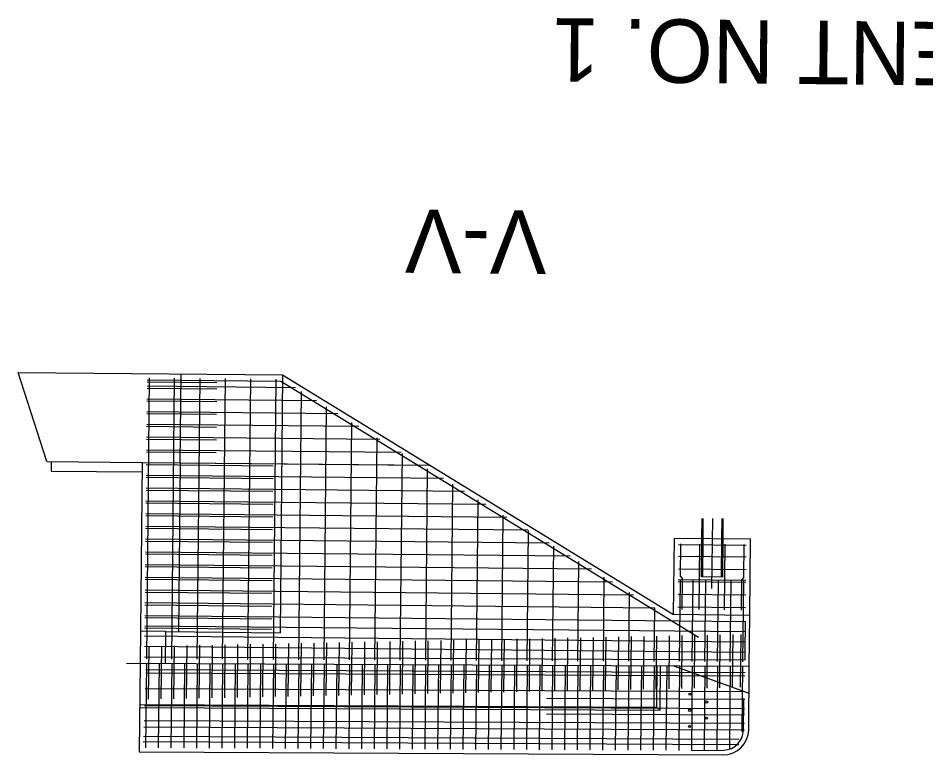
# Model space of a CAD drawing. Extents: x 631918 to 632319, y 373181 to 373282.
# Drawn here: x 632132.56 to 632168.31, y 373221.98 to 373251.01 of the extents above; entities that cross this region are included whole.
import ezdxf

# ---------------------------------------------------------------- set-up
doc = ezdxf.new("R2010")
doc.units = 0
for name, color, linetype in [('B_Boring', 7, 'Continuous'), ('BD-PROP-COSS', 7, 'Continuous'), ('BD-REMOVE', 7, 'Continuous'), ('R_Border_Scale', 7, 'Continuous'), ('R_Road Edge of Travel', 7, 'Continuous'), ('R_Shade Removal', 7, 'Continuous'), ('R_Wall', 7, 'Continuous')]:
    doc.layers.add(name, color=color, linetype=linetype)

msp = doc.modelspace()

# ---------------------------------------------------------------- linework, layer by layer
at = {"layer": 'B_Boring'}
for p, q in [((632157.719, 373223.868), (632157.735, 373225.496)), ((632157.842, 373223.745), (632157.86, 373225.495)), ((632137.342, 373223.846), (632157.842, 373223.745)), ((632137.344, 373223.969), (632157.719, 373223.868)), ((632157.719, 373223.868), (632157.842, 373223.745))]:
    msp.add_line(p, q, dxfattribs=at)
at = {"layer": 'BD-PROP-COSS'}
for p, q in [((632137.721, 373236.838), (632137.611, 373225.763)), ((632140.386, 373236.645), (632137.636, 373236.673)), ((632137.637, 373236.756), (632142.901, 373236.704)), ((632138.611, 373225.758), (632138.721, 373236.828)), ((632139.611, 373225.753), (632139.721, 373236.818)), ((632140.611, 373225.748), (632140.721, 373236.809)), ((632141.611, 373225.743), (632141.721, 373236.799)), ((632142.611, 373225.738), (632142.721, 373236.789)), ((632142.901, 373236.704), (632159.355, 373226.616)), ((632140.384, 373236.395), (632137.634, 373236.423)), ((632143.478, 373236.448), (632137.635, 373236.506)), ((632143.611, 373225.733), (632143.716, 373236.301)), ((632140.379, 373235.893), (632137.629, 373235.92)), ((632144.311, 373235.937), (632137.63, 373236.004)), ((632145.144, 373235.427), (632137.625, 373235.501)), ((632144.611, 373225.728), (632144.71, 373235.692)), ((632140.374, 373235.391), (632137.624, 373235.418)), ((632140.369, 373234.888), (632137.619, 373234.916)), ((632145.977, 373234.916), (632137.62, 373234.999)), ((632145.611, 373225.724), (632145.704, 373235.083)), ((632140.364, 373234.386), (632137.614, 373234.413)), ((632146.809, 373234.405), (632137.615, 373234.497)), ((632146.611, 373225.719), (632146.698, 373234.473)), ((632140.359, 373233.884), (632137.609, 373233.911)), ((632147.642, 373233.895), (632137.61, 373233.994)), ((632147.611, 373225.714), (632147.692, 373233.864)), ((632142.604, 373233.359), (632137.604, 373233.409)), ((632148.475, 373233.384), (632137.605, 373233.492)), ((632149.308, 373232.873), (632137.6, 373232.99)), ((632148.611, 373225.709), (632148.686, 373233.255)), ((632142.599, 373232.857), (632137.599, 373232.906)), ((632149.611, 373225.704), (632149.68, 373232.645)), ((632142.594, 373232.354), (632137.594, 373232.404)), ((632150.141, 373232.363), (632137.595, 373232.488)), ((632142.589, 373231.852), (632137.589, 373231.902)), ((632150.974, 373231.852), (632137.59, 373231.985)), ((632150.611, 373225.699), (632150.674, 373232.036)), ((632142.584, 373231.35), (632137.584, 373231.4)), ((632151.807, 373231.342), (632137.585, 373231.483)), ((632151.611, 373225.694), (632151.668, 373231.426)), ((632142.579, 373230.848), (632137.579, 373230.897)), ((632152.64, 373230.831), (632137.58, 373230.981)), ((632152.611, 373225.689), (632152.662, 373230.817)), ((632153.473, 373230.32), (632137.575, 373230.478)), ((632142.574, 373230.345), (632137.574, 373230.395)), ((632153.611, 373225.684), (632153.656, 373230.208)), ((632161.24, 373230.229), (632158.574, 373230.256)), ((632158.645, 373229.005), (632158.657, 373230.297)), ((632159.382, 373227.706), (632159.407, 373230.289)), ((632160.382, 373227.696), (632160.407, 373230.279)), ((632161.145, 373228.98), (632161.157, 373230.272)), ((632142.569, 373229.843), (632137.569, 373229.893)), ((632154.306, 373229.81), (632137.57, 373229.976)), ((632161.236, 373229.771), (632158.569, 373229.797)), ((632142.564, 373229.341), (632137.564, 373229.39)), ((632155.139, 373229.299), (632137.565, 373229.474)), ((632154.611, 373225.679), (632154.65, 373229.598)), ((632161.231, 373229.271), (632158.564, 373229.297)), ((632142.559, 373228.838), (632137.559, 373228.888)), ((632155.971, 373228.788), (632137.56, 373228.972)), ((632155.611, 373225.674), (632155.644, 373228.989)), ((632161.226, 373228.771), (632158.559, 373228.797)), ((632161.227, 373228.854), (632158.56, 373228.881)), ((632158.611, 373225.672), (632158.643, 373228.88)), ((632158.645, 373229.005), (632158.727, 373228.921)), ((632158.715, 373227.713), (632158.727, 373228.921)), ((632159.111, 373225.667), (632159.143, 373228.875)), ((632159.611, 373225.662), (632159.643, 373228.87)), ((632160.111, 373225.657), (632160.143, 373228.865)), ((632160.611, 373225.652), (632160.643, 373228.86)), ((632161.048, 373227.689), (632161.06, 373228.898)), ((632161.145, 373228.98), (632161.06, 373228.898)), ((632161.111, 373225.647), (632161.143, 373228.855)), ((632142.554, 373228.336), (632137.554, 373228.386)), ((632156.804, 373228.278), (632137.555, 373228.469)), ((632156.611, 373225.669), (632156.638, 373228.38)), ((632157.637, 373227.767), (632137.55, 373227.967)), ((632161.221, 373228.271), (632158.554, 373228.297)), ((632142.549, 373227.834), (632137.549, 373227.884)), ((632157.611, 373225.664), (632157.632, 373227.77)), ((632161.216, 373227.771), (632158.549, 373227.797)), ((632142.544, 373227.332), (632137.544, 373227.381)), ((632161.21, 373227.229), (632137.545, 373227.465)), ((632142.54, 373226.927), (632137.54, 373226.977)), ((632161.206, 373226.825), (632137.541, 373227.06)), ((632161.202, 373226.42), (632137.537, 373226.655)), ((632151.203, 373226.53), (632151.182, 373224.447)), ((632151.703, 373226.54), (632151.682, 373224.457)), ((632152.203, 373226.55), (632152.183, 373224.467)), ((632152.703, 373226.56), (632152.683, 373224.477)), ((632153.203, 373226.57), (632153.183, 373224.487)), ((632153.704, 373226.58), (632153.683, 373224.497)), ((632154.204, 373226.59), (632154.183, 373224.507)), ((632154.704, 373226.6), (632154.683, 373224.517)), ((632155.204, 373226.61), (632155.183, 373224.527)), ((632155.704, 373226.62), (632155.683, 373224.537)), ((632156.204, 373226.63), (632156.184, 373224.547)), ((632156.704, 373226.64), (632156.684, 373224.557)), ((632157.204, 373226.65), (632157.184, 373224.567)), ((632157.705, 373226.66), (632157.684, 373224.577)), ((632158.205, 373226.67), (632158.184, 373224.587)), ((632158.705, 373226.68), (632158.684, 373224.597)), ((632159.205, 373226.691), (632159.184, 373224.607)), ((632159.705, 373226.701), (632159.684, 373224.617)), ((632160.205, 373226.711), (632160.185, 373224.627)), ((632160.705, 373226.721), (632160.685, 373224.637)), ((632161.018, 373224.644), (632161.039, 373226.727)), ((632161.198, 373226.015), (632137.533, 373226.251)), ((632137.7, 373226.259), (632137.679, 373224.176)), ((632138.2, 373226.269), (632138.179, 373224.186)), ((632138.7, 373226.279), (632138.679, 373224.196)), ((632139.2, 373226.289), (632139.179, 373224.206)), ((632139.7, 373226.299), (632139.679, 373224.216)), ((632140.2, 373226.309), (632140.18, 373224.226)), ((632140.7, 373226.319), (632140.68, 373224.236)), ((632141.201, 373226.329), (632141.18, 373224.246)), ((632141.701, 373226.34), (632141.68, 373224.256)), ((632142.201, 373226.35), (632142.18, 373224.266)), ((632142.701, 373226.36), (632142.68, 373224.276)), ((632143.201, 373226.37), (632143.18, 373224.286)), ((632143.701, 373226.38), (632143.68, 373224.296)), ((632144.201, 373226.39), (632144.181, 373224.306)), ((632144.701, 373226.4), (632144.681, 373224.316)), ((632145.202, 373226.41), (632145.181, 373224.326)), ((632145.702, 373226.42), (632145.681, 373224.337)), ((632146.202, 373226.43), (632146.181, 373224.347)), ((632146.702, 373226.44), (632146.681, 373224.357)), ((632147.202, 373226.45), (632147.181, 373224.367)), ((632147.702, 373226.46), (632147.681, 373224.377)), ((632148.202, 373226.47), (632148.182, 373224.387)), ((632148.702, 373226.48), (632148.682, 373224.397)), ((632149.202, 373226.49), (632149.182, 373224.407)), ((632149.703, 373226.5), (632149.682, 373224.417)), ((632150.203, 373226.51), (632150.182, 373224.427)), ((632150.703, 373226.52), (632150.682, 373224.437)), ((632137.529, 373225.846), (632161.196, 373225.729)), ((632137.61, 373225.595), (632137.577, 373222.262)), ((632138.11, 373225.593), (632138.077, 373222.26)), ((632138.61, 373225.59), (632138.577, 373222.257)), ((632139.11, 373225.588), (632139.077, 373222.255)), ((632139.61, 373225.585), (632139.577, 373222.252)), ((632140.11, 373225.583), (632140.077, 373222.25)), ((632140.61, 373225.58), (632140.577, 373222.247)), ((632141.11, 373225.578), (632141.077, 373222.245)), ((632141.61, 373225.575), (632141.577, 373222.242)), ((632142.11, 373225.573), (632142.077, 373222.24)), ((632142.61, 373225.57), (632142.577, 373222.237)), ((632143.11, 373225.568), (632143.077, 373222.235)), ((632143.61, 373225.565), (632143.577, 373222.232)), ((632144.11, 373225.563), (632144.077, 373222.23)), ((632144.61, 373225.567), (632144.577, 373222.227)), ((632145.11, 373225.558), (632145.077, 373222.225)), ((632145.61, 373225.556), (632145.577, 373222.222)), ((632146.11, 373225.553), (632146.077, 373222.22)), ((632146.61, 373225.551), (632146.577, 373222.217)), ((632147.11, 373225.548), (632147.077, 373222.215)), ((632147.61, 373225.546), (632147.577, 373222.213)), ((632148.11, 373225.543), (632148.077, 373222.21)), ((632148.61, 373225.541), (632148.577, 373222.208)), ((632149.11, 373225.538), (632149.077, 373222.205)), ((632149.61, 373225.536), (632149.577, 373222.203)), ((632150.11, 373225.533), (632150.077, 373222.2)), ((632150.61, 373225.531), (632150.577, 373222.198)), ((632151.11, 373225.528), (632151.077, 373222.195)), ((632151.61, 373225.526), (632151.577, 373222.193)), ((632152.11, 373225.523), (632152.077, 373222.19)), ((632152.61, 373225.521), (632152.577, 373222.188)), ((632153.11, 373225.519), (632153.077, 373222.185)), ((632153.61, 373225.516), (632153.577, 373222.183)), ((632154.11, 373225.514), (632154.077, 373222.18)), ((632154.61, 373225.511), (632154.577, 373222.178)), ((632155.11, 373225.509), (632155.077, 373222.175)), ((632155.61, 373225.506), (632155.577, 373222.173)), ((632156.11, 373225.504), (632156.077, 373222.171)), ((632156.61, 373225.501), (632156.577, 373222.168)), ((632157.11, 373225.499), (632157.077, 373222.166)), ((632157.61, 373225.496), (632157.577, 373222.163)), ((632158.11, 373225.494), (632158.077, 373222.161)), ((632158.61, 373225.491), (632158.577, 373222.158)), ((632159.11, 373225.489), (632159.077, 373222.156)), ((632159.61, 373225.486), (632159.577, 373222.153)), ((632160.11, 373225.484), (632160.077, 373222.151)), ((632160.61, 373225.482), (632160.577, 373222.219)), ((632161.084, 373222.896), (632161.11, 373225.479)), ((632137.58, 373225.217), (632161.189, 373225.1)), ((632137.584, 373225.341), (632161.191, 373225.224)), ((632137.558, 373224.592), (632161.183, 373224.475)), ((632153.388, 373224.221), (632161.18, 373224.183)), ((632161.126, 373222.957), (632161.139, 373224.207)), ((632137.535, 373223.925), (632161.176, 373223.809)), ((632137.515, 373223.342), (632161.171, 373223.225)), ((632153.366, 373223.597), (632161.174, 373223.558)), ((632137.506, 373223.092), (632161.168, 373222.975)), ((632137.493, 373222.717), (632160.942, 373222.601)), ((632137.485, 373222.509), (632160.941, 373222.393)), ((632159.101, 373222.148), (632160.351, 373222.173))]:
    msp.add_line(p, q, dxfattribs=at)
msp.add_arc((632160.335, 373222.965), 0.792, 271.1487, 359.4304, dxfattribs=at)
at = {"layer": 'R_Border_Scale'}
for p, q in [((632138.938, 373233.493), (632138.973, 373236.993)), ((632137.438, 373233.508), (632138.938, 373233.493)), ((632138.938, 373233.493), (632148.776, 373233.395)), ((632138.372, 373226.841), (632137.372, 373226.851)), ((632136.823, 373225.599), (632161.36, 373225.478))]:
    msp.add_line(p, q, dxfattribs=at)
at = {"layer": 'R_Road Edge of Travel'}
for p, q in [((632159.493, 373230.497), (632159.501, 373231.3)), ((632159.54, 373230.496), (632159.548, 373231.3)), ((632160.279, 373230.489), (632160.287, 373231.292)), ((632160.326, 373230.488), (632160.334, 373231.292)), ((632159.478, 373228.997), (632159.493, 373230.497)), ((632159.525, 373228.996), (632159.54, 373230.496)), ((632160.264, 373228.989), (632160.279, 373230.489)), ((632160.311, 373228.988), (632160.326, 373230.488)), ((632160.311, 373228.988), (632159.478, 373228.997))]:
    msp.add_line(p, q, dxfattribs=at)
at = {"layer": 'R_Shade Removal'}
for p, q in [((632133.689, 373233.545), (632132.557, 373237.056)), ((632132.557, 373237.056), (632142.973, 373236.953)), ((632142.973, 373236.953), (632142.872, 373226.797)), ((632142.973, 373236.953), (632158.38, 373227.507)), ((632133.689, 373233.545), (632137.438, 373233.508)), ((632133.855, 373233.543), (632133.851, 373233.168)), ((632137.438, 373233.508), (632137.36, 373225.596)), ((632138.938, 373233.493), (632138.872, 373226.836)), ((632133.851, 373233.168), (632137.435, 373233.133)), ((632158.38, 373227.507), (632158.41, 373230.507)), ((632161.409, 373230.478), (632158.41, 373230.507)), ((632161.38, 373227.478), (632161.409, 373230.478)), ((632161.38, 373227.478), (632158.38, 373227.507)), ((632161.36, 373225.478), (632161.38, 373227.478)), ((632161.206, 373226.825), (632161.21, 373227.229)), ((632138.36, 373225.591), (632138.372, 373226.841)), ((632138.372, 373226.841), (632142.872, 373226.797)), ((632161.202, 373226.42), (632161.206, 373226.825)), ((632161.198, 373226.015), (632161.202, 373226.42)), ((632161.196, 373225.729), (632161.198, 373226.015)), ((632137.36, 373225.596), (632137.325, 373222.097)), ((632161.349, 373224.394), (632158.36, 373225.493)), ((632161.335, 373222.973), (632161.36, 373225.478)), ((632137.325, 373222.097), (632160.33, 373221.983))]:
    msp.add_line(p, q, dxfattribs=at)
for centre in [(632159.015, 373224.375), (632159.679, 373224.067), (632159.009, 373223.739), (632159.673, 373223.431), (632159.003, 373223.104)]:
    msp.add_circle(centre, 0.0417, dxfattribs=at)
msp.add_arc((632160.335, 373222.983), 1, 269.7168, 359.4304, dxfattribs=at)
at = {"layer": 'R_Wall'}
msp.add_line((632159.89, 373228.533), (632159.917, 373231.296), dxfattribs=at)

# ---------------------------------------------------------------- texts
at = {"layer": 'BD-REMOVE'}
for s, p in [('BENT NO. 1', (632172.191, 373250.83)), ('V-V', (632153.386, 373243.424))]:
    msp.add_text(s, height=2.5, rotation=179.4304, dxfattribs=at).set_placement(p)

doc.saveas('drawing.dxf')
